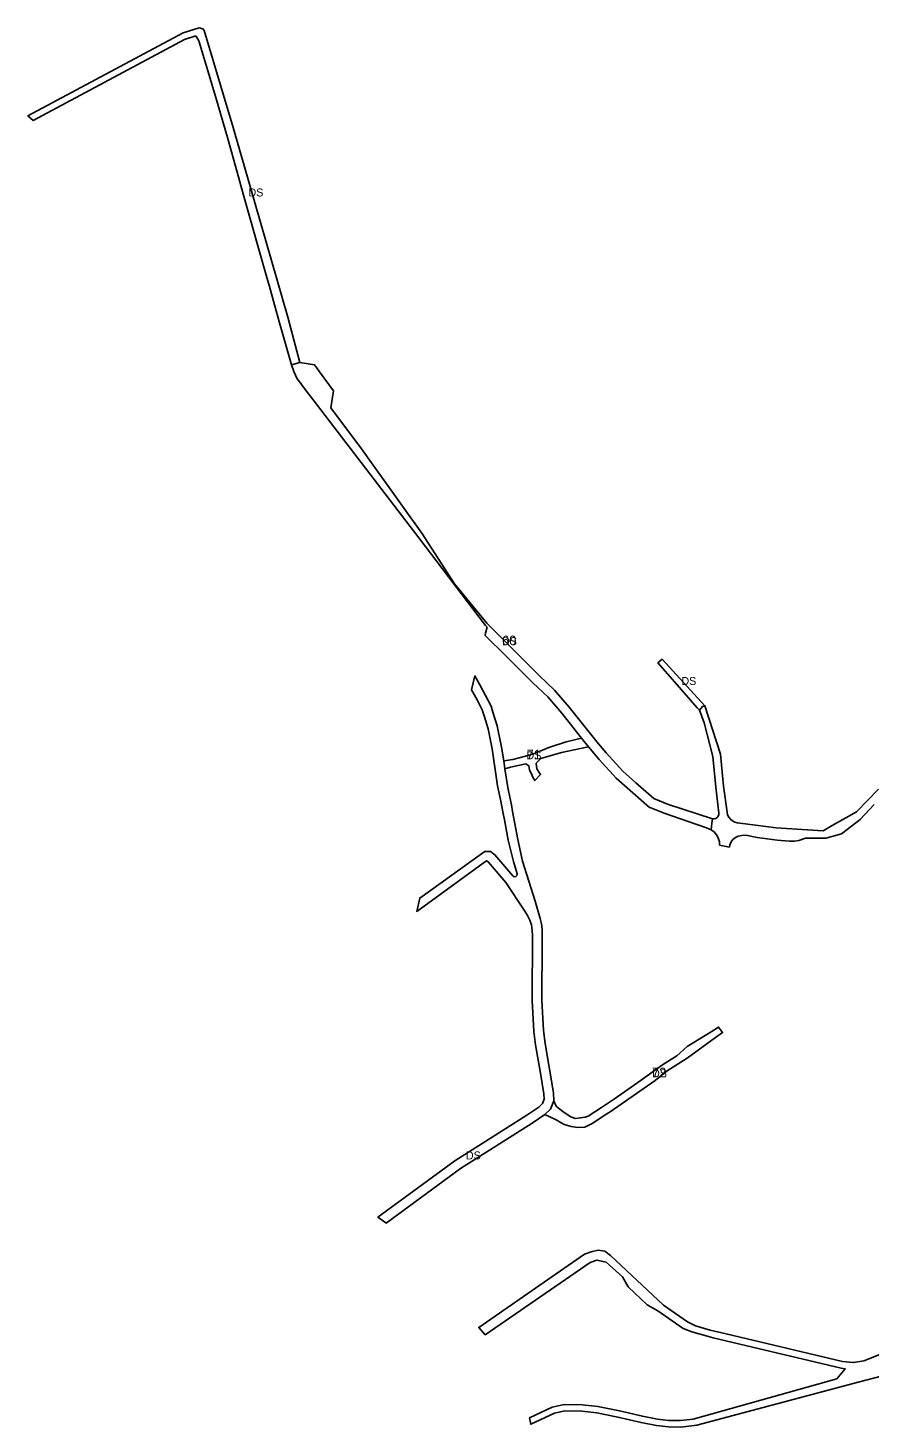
# Model space of a CAD drawing. Extents: x -535435 to -532834, y -1165802 to -1163866.
# Drawn here: x -535435 to -534910, y -1165594 to -1164720 of the extents above; entities that cross this region are included whole.
import ezdxf

# ---------------------------------------------------------------- set-up
doc = ezdxf.new("R2010")
doc.units = 0
for name, color, linetype in [('90320013', 7, 'Continuous'), ('90320023', 7, 'Continuous'), ('90450013', 7, 'Continuous'), ('ID_navrh', 7, 'Continuous')]:
    doc.layers.add(name, color=color, linetype=linetype)

msp = doc.modelspace()

# ---------------------------------------------------------------- linework, layer by layer
at = {"layer": '90320013'}
for points in [[(-535330.07, -1164724.66), (-535336.95, -1164727.03), (-535431.57, -1164777.51), (-535434.81, -1164774.69), (-535337.8, -1164722.86), (-535327.926, -1164719.801), (-535325.538, -1164720.285), (-535324.72, -1164721.28), (-535306.74, -1164781.96), (-535272.55, -1164900.37), (-535264.937, -1164928.872), (-535270.21, -1164930.28), (-535277.63, -1164903.97), (-535280.81, -1164892.67), (-535284.01, -1164881.32), (-535286.04, -1164874.13), (-535291.17, -1164855.92), (-535295.73, -1164839.71), (-535300.1, -1164824.22), (-535304.15, -1164809.81), (-535310.26, -1164788.12), (-535317.16, -1164764.78), (-535322.98, -1164745.04), (-535328.05, -1164727.88)], [(-535015.48, -1165146.04), (-535016.81, -1165144.52), (-535030.794, -1165128.551), (-535041.39, -1165116.45), (-535038.78, -1165114.13), (-535012, -1165143.18), (-535013.47, -1165143.59)], [(-535148.99, -1165136.793), (-535145.543, -1165143.469), (-535144.388, -1165147.195), (-535141.761, -1165155.672), (-535139.073, -1165168.99), (-535137.699, -1165177.679), (-535136.921, -1165182.604), (-535135.082, -1165194.239), (-535134.644, -1165196.443), (-535132.906, -1165205.189), (-535132.101, -1165209.239), (-535128.956, -1165226.673), (-535125.87, -1165240.38), (-535117.999, -1165265.365), (-535114.922, -1165276.165), (-535114.34, -1165278.52), (-535113.917, -1165280.968), (-535113.669, -1165283.44), (-535113.598, -1165285.864), (-535113.63, -1165291.112), (-535113.849, -1165327.11), (-535112.849, -1165346.141), (-535111.891, -1165354.083), (-535109.318, -1165368.871), (-535106.611, -1165385.025), (-535106.384, -1165390.083), (-535108.428, -1165395.194), (-535112.025, -1165398.608), (-535119.956, -1165403.95), (-535164.747, -1165432.339), (-535211.12, -1165466.396), (-535211.33, -1165466.2), (-535216.209, -1165462.689), (-535168.133, -1165427.381), (-535123.192, -1165398.897), (-535115.815, -1165393.932), (-535113.511, -1165391.746), (-535112.436, -1165389.057), (-535112.589, -1165385.655), (-535114.738, -1165372.776), (-535117.829, -1165354.957), (-535118.831, -1165346.659), (-535119.85, -1165327.25), (-535119.6, -1165286.314), (-535120.06, -1165281.704), (-535120.362, -1165280.089), (-535121.35, -1165277.051), (-535122.724, -1165274.167), (-535124.443, -1165271.506), (-535136.396, -1165253.54), (-535147.292, -1165240.661), (-535148.513, -1165240.068), (-535150.484, -1165241.561), (-535192.03, -1165271.675), (-535190.12, -1165263.37), (-535151.45, -1165235.77), (-535149.382, -1165234.317), (-535145.859, -1165234.181), (-535143.165, -1165236.25), (-535131.919, -1165249.542), (-535131.052, -1165250.047), (-535130.061, -1165249.893), (-535129.389, -1165249.15), (-535129.335, -1165248.149), (-535131.592, -1165240.499), (-535134.967, -1165227.138), (-535137.13, -1165214.5), (-535137.971, -1165210.486), (-535139.693, -1165201.821), (-535141.609, -1165193.118), (-535144.987, -1165170.01), (-535147.452, -1165157.578), (-535149.965, -1165149.468), (-535151.117, -1165145.751), (-535154.355, -1165139.487), (-535157.001, -1165134.64), (-535157.813, -1165133.153), (-535155.665, -1165124.565), (-535152.58, -1165130.217)]]:
    msp.add_lwpolyline(points, close=True, dxfattribs=at)
msp.add_lwpolyline([(-534901.88, -1165561.94), (-534915.56, -1165565.61), (-535017.005, -1165592.619), (-535027.066, -1165593.763), (-535034.7, -1165593.677), (-535042.228, -1165592.817), (-535051.857, -1165590.952), (-535066.313, -1165587.566), (-535079.591, -1165584.808), (-535088.941, -1165583.857), (-535099.519, -1165583.706), (-535106.051, -1165585.159), (-535120.744, -1165592.052), (-535121.655, -1165588.062), (-535107.35, -1165581.35), (-535099.93, -1165579.7), (-535088.71, -1165579.86), (-535078.98, -1165580.85), (-535065.45, -1165583.66), (-535051.02, -1165587.04), (-535041.62, -1165588.86), (-535034.45, -1165589.68), (-535027.27, -1165589.76), (-535019.35, -1165588.86), (-534929.63, -1165563.61), (-534924.332, -1165557.424), (-534926.87, -1165557.06), (-535006.933, -1165537.976), (-535009.77, -1165537.3), (-535020.09, -1165534.38), (-535025.58, -1165532.21), (-535041.43, -1165521.13), (-535048.04, -1165517.37), (-535059.98, -1165506.16), (-535063.55, -1165500.03), (-535073.7, -1165490.85), (-535079.48, -1165489.46), (-535083.65, -1165491.01), (-535149.25, -1165536.15), (-535153.29, -1165531.56), (-535087.18, -1165485.86), (-535082.4, -1165484.03), (-535078.527, -1165483.386), (-535074.543, -1165483.89), (-535070.93, -1165486.65), (-535037.98, -1165517.6), (-535022.95, -1165527.99), (-535017.91, -1165530.5), (-535008.78, -1165533.19), (-534998.84, -1165535.55), (-534926.03, -1165552.84), (-534919.44, -1165553.53), (-534919.2, -1165553.5), (-534912.68, -1165552.42), (-534877.24, -1165538.36)], dxfattribs=at)
at = {"layer": '90320023'}
for points in [[(-535168.377, -1165067.011), (-535148.121, -1165091.686), (-535115.229, -1165124.489), (-535105.854, -1165133.419), (-535096.773, -1165144.045), (-535078.389, -1165167.024), (-535073.739, -1165172.685), (-535063.193, -1165184.14), (-535055.086, -1165191.249), (-535043.899, -1165201.06), (-535035.407, -1165204.645), (-535007.209, -1165213.768), (-535007.592, -1165216.549), (-535008.151, -1165220.618), (-535010.939, -1165219.424), (-535017.131, -1165217.289), (-535037.55, -1165210.25), (-535045.87, -1165206.9), (-535046.59, -1165206.68), (-535067.39, -1165188.44), (-535078.153, -1165176.749), (-535084.682, -1165168.809), (-535089.002, -1165163.415), (-535101.402, -1165147.865), (-535110.216, -1165137.551), (-535119.396, -1165128.806), (-535128.931, -1165119.482), (-535141.331, -1165107.067), (-535143.98, -1165104.415), (-535149.344, -1165099.292), (-535148.98, -1165097.84), (-535148.04, -1165094.04), (-535149, -1165092.96), (-535191.37, -1165037.5), (-535264.1, -1164942.33), (-535264.287, -1164942.086), (-535266.73, -1164938.9), (-535268.776, -1164934.471), (-535270.21, -1164930.28), (-535264.937, -1164928.872), (-535255.808, -1164930.235), (-535254.681, -1164931.794), (-535252.719, -1164934.506), (-535244.088, -1164946.44), (-535245.617, -1164957.123), (-535226.518, -1164982.739), (-535199.872, -1165019.877), (-535188.741, -1165035.391)], [(-535089.002, -1165163.415), (-535084.682, -1165168.809), (-535101.55, -1165172.42), (-535114.59, -1165176.22), (-535117.507, -1165179.149), (-535117.077, -1165182.508), (-535114.67, -1165186.14), (-535118.3, -1165189.93), (-535119.491, -1165187.733), (-535119.975, -1165186.84), (-535121.499, -1165183.162), (-535121.98, -1165180.725), (-535123.795, -1165179.535), (-535133.443, -1165181.633), (-535136.921, -1165182.604), (-535137.699, -1165177.679), (-535136.049, -1165177.441), (-535131.907, -1165176.691), (-535124.139, -1165174.765), (-535120.442, -1165173.67), (-535119.161, -1165173.236), (-535118.727, -1165173.09), (-535113.551, -1165171.039), (-535109.532, -1165169.282), (-535098.68, -1165165.83)], [(-535068.421, -1165388.794), (-535053.883, -1165378.489), (-535038.579, -1165367.539), (-535029.62, -1165361.786), (-535023.08, -1165356.13), (-535008.17, -1165346.93), (-535003.447, -1165343.979), (-535000.94, -1165347.399), (-535005.398, -1165350.5), (-535023.047, -1165363.292), (-535035.57, -1165371.22), (-535043.045, -1165377.297), (-535066.459, -1165393.597), (-535071.799, -1165397.236), (-535073.648, -1165398.418), (-535081.996, -1165403.907), (-535087.093, -1165406.349), (-535091.323, -1165406.681), (-535095.444, -1165405.995), (-535099.848, -1165404.852), (-535102.855, -1165403.084), (-535105, -1165401.823), (-535112.025, -1165398.608), (-535108.428, -1165395.194), (-535106.384, -1165390.083), (-535104.973, -1165393.334), (-535103.387, -1165394.572), (-535099.891, -1165397.3), (-535095.698, -1165400.055), (-535092.83, -1165401.015), (-535089.815, -1165400.622), (-535086.711, -1165400.218), (-535084.898, -1165399.647), (-535076.515, -1165394.257)]]:
    msp.add_lwpolyline(points, close=True, dxfattribs=at)
at = {"layer": '90450013'}
msp.add_lwpolyline([(-534906.33, -1165204.96), (-534915.11, -1165214.3), (-534926.75, -1165223.13), (-534936.53, -1165225.98), (-534949.227, -1165225.98), (-534953.275, -1165227.27), (-534956.161, -1165227.718), (-534959.082, -1165227.751), (-534966.878, -1165227.187), (-534979.286, -1165225.462), (-534986.553, -1165224.068), (-534988.908, -1165224.168), (-534991.219, -1165224.637), (-534992.956, -1165225.495), (-534994.498, -1165226.668), (-534995.639, -1165228.234), (-534996.421, -1165230.007), (-534996.705, -1165231.467), (-535002.864, -1165230.269), (-535002.91, -1165228.216), (-535003.441, -1165226.232), (-535004.369, -1165224.4), (-535005.995, -1165222.244), (-535008.151, -1165220.618), (-535007.592, -1165216.549), (-535007.209, -1165213.768), (-535006.177, -1165213.825), (-535005.163, -1165213.554), (-535004.284, -1165212.976), (-535003.631, -1165212.151), (-535003.272, -1165211.166), (-535003.229, -1165210.204), (-535005.25, -1165194.06), (-535007.1, -1165174.89), (-535012.56, -1165153.94), (-535015.48, -1165146.04), (-535013.47, -1165143.59), (-535012, -1165143.18), (-535002.34, -1165173.49), (-535000.3, -1165193.52), (-534998.188, -1165209.776), (-534997.805, -1165211.356), (-534997.089, -1165212.819), (-534996.073, -1165214.093), (-534994.807, -1165215.118), (-534993.349, -1165215.845), (-534991.771, -1165216.24), (-534986.89, -1165216.91), (-534967.57, -1165219.55), (-534938.22, -1165221.25), (-534932.44, -1165217.99), (-534917.33, -1165209.45), (-534903.6, -1165195.4)], dxfattribs=at)

# ---------------------------------------------------------------- texts
at = {"layer": '90320013'}
for rotation, p in [(0, (-535297.0847, -1164825.0405)), (0.0000001, (-535026.695, -1165130.2356)), (360, (-535161.2965, -1165426.6))]:
    msp.add_text('DS', height=5, rotation=rotation, dxfattribs=at).set_placement(p)
at = {"layer": '90320023'}
for rotation, p in [(359.9999999, (-535138.7095, -1165105.3819)), (0.0000001, (-535123.4365, -1165176.6725)), (360, (-535045.0467, -1165375.33))]:
    msp.add_text('DS', height=5, rotation=rotation, dxfattribs=at).set_placement(p)
at = {"layer": 'ID_navrh'}
for s, rotation, p in [('60', 0, (-535138.7095, -1165105.3819)), ('71', 0.0000001, (-535123.4365, -1165176.6725)), ('72', 360, (-535045.0467, -1165375.33))]:
    msp.add_text(s, height=6, rotation=rotation, dxfattribs=at).set_placement(p)

doc.saveas('drawing.dxf')
